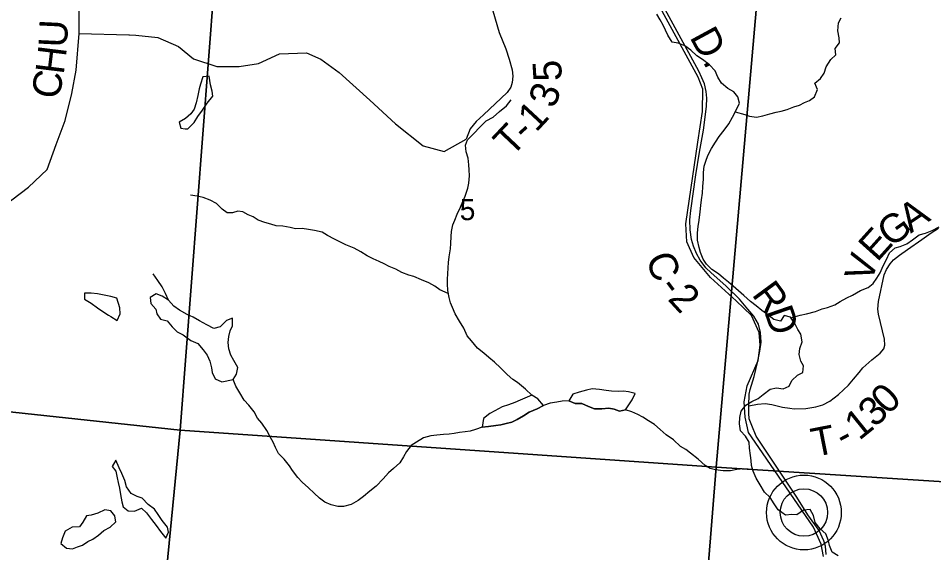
# Model space of a CAD drawing. Extents: x 0 to 42, y 0 to 22.
# Drawn here: x 5.439 to 6.349, y 16.58 to 17.112 of the extents above; entities that cross this region are included whole.
import ezdxf

# ---------------------------------------------------------------- set-up
doc = ezdxf.new("R2010")
doc.units = 0
for name, color, linetype in [('GM_X_County_Road', 7, 'Continuous'), ('GM_X_County_Road_Text', 7, 'Continuous'), ('GM_X_Minor_Lake', 7, 'Continuous'), ('GM_X_Minor_River', 7, 'Continuous'), ('GM_X_Rail_Line', 7, 'Continuous'), ('GM_X_Section', 7, 'Continuous'), ('GM_X_Section_Text', 7, 'Continuous'), ('GM_X_Township_Road', 7, 'Continuous'), ('GM_X_Township_Road_Text', 7, 'Continuous'), ('GM_X_Unincorporated', 7, 'Continuous'), ('GM_X_Unincorporated_Location', 7, 'Continuous')]:
    doc.layers.add(name, color=color, linetype=linetype)

msp = doc.modelspace()

# ---------------------------------------------------------------- linework, layer by layer
at = {"layer": 'GM_X_County_Road'}
msp.add_lwpolyline([(6.24237, 16.57834), (6.24164, 16.58663), (6.24003, 16.59225), (6.23522, 16.60227), (6.22412, 16.61791), (6.21303, 16.63543), (6.17849, 16.68713), (6.17274, 16.69623), (6.16813, 16.70676), (6.16578, 16.71352), (6.1653, 16.71899), (6.16523, 16.72628), (6.16569, 16.73809), (6.16677, 16.74257), (6.17067, 16.75545), (6.17416, 16.7707), (6.17625, 16.78068), (6.17756, 16.78978), (6.17679, 16.79943), (6.17482, 16.80754), (6.17043, 16.81566), (6.16429, 16.82268), (6.15586, 16.83252), (6.14247, 16.84582), (6.12767, 16.85854), (6.12268, 16.86354), (6.11692, 16.87115), (6.11341, 16.87795), (6.11034, 16.8853), (6.10836, 16.89177), (6.10683, 16.90153), (6.1065, 16.91151), (6.1076, 16.92072), (6.11264, 16.95603), (6.11615, 16.97884), (6.12034, 17.00047), (6.12328, 17.02413), (6.12361, 17.03225), (6.12284, 17.03915), (6.12109, 17.0465), (6.11856, 17.05275), (6.11549, 17.05922), (6.0725, 17.13851)], dxfattribs=at)
at = {"layer": 'GM_X_Minor_Lake'}
for points in [[(5.62834, 17.05424), (5.6221, 17.05367), (5.61984, 17.04628), (5.61852, 17.04155), (5.6172, 17.03491), (5.61569, 17.02771), (5.61343, 17.02146), (5.61022, 17.01672), (5.60494, 17.01217), (5.59871, 17.00857), (5.60041, 17.00251), (5.60459, 17.00205)], [(5.60459, 17.00205), (5.6074, 17.00175), (5.61363, 17.00819), (5.61721, 17.01407), (5.62174, 17.02051), (5.62665, 17.02753), (5.63212, 17.03435), (5.63155, 17.03928), (5.62985, 17.04572), (5.62834, 17.05424)], [(5.53666, 16.83348), (5.5308, 16.83499), (5.51758, 16.83764), (5.51116, 16.83839), (5.50455, 16.83858), (5.50456, 16.83252), (5.51117, 16.82835), (5.5174, 16.82399), (5.52382, 16.81964), (5.5284, 16.81666)], [(5.58799, 16.83157), (5.5816, 16.83539), (5.57575, 16.83766), (5.5697, 16.83424), (5.57046, 16.82818), (5.57556, 16.8225), (5.57632, 16.81776), (5.5801, 16.81246), (5.58671, 16.81094), (5.59162, 16.80507), (5.59653, 16.79996), (5.60258, 16.79693), (5.61032, 16.79144), (5.61712, 16.78841), (5.6226, 16.78197), (5.62638, 16.77685), (5.62903, 16.77079), (5.63092, 16.76416), (5.63149, 16.75943), (5.63432, 16.75317), (5.64093, 16.75033), (5.65228, 16.75246)], [(5.5284, 16.81666), (5.53081, 16.81509), (5.53705, 16.81131), (5.54006, 16.81775), (5.5395, 16.82381), (5.53666, 16.83348)], [(5.65228, 16.75246), (5.6557, 16.75794), (5.65686, 16.76456), (5.65311, 16.7714), (5.64992, 16.77672), (5.64806, 16.78317), (5.64733, 16.78943), (5.64812, 16.7953), (5.64946, 16.80098), (5.65175, 16.80608), (5.65159, 16.81347), (5.64573, 16.81141), (5.63946, 16.80481), (5.63322, 16.80313), (5.62625, 16.80695), (5.61889, 16.81078), (5.61248, 16.81441), (5.60664, 16.81727), (5.5991, 16.82148), (5.59326, 16.82567), (5.58799, 16.83157)], [(5.9, 16.70511), (5.90642, 16.70584), (5.91361, 16.70675), (5.91871, 16.70749), (5.92401, 16.70879), (5.9295, 16.71009), (5.93499, 16.71272), (5.94124, 16.71648), (5.94693, 16.72006), (5.95469, 16.72324), (5.96112, 16.72662), (5.9553, 16.73328), (5.94946, 16.73691)], [(5.94946, 16.73691), (5.93799, 16.73186), (5.93251, 16.72978), (5.92628, 16.7275), (5.91986, 16.72523), (5.91269, 16.72144), (5.90759, 16.71878), (5.90136, 16.71366), (5.9, 16.70511)], [(6.04256, 16.72228), (6.04922, 16.73228), (6.05224, 16.73853), (6.04544, 16.74042), (6.04053, 16.74099), (6.03562, 16.74061), (6.02882, 16.74098), (6.02353, 16.74174), (6.01673, 16.7425), (6.00956, 16.74325), (6.0037, 16.74211), (5.99653, 16.74003), (5.99011, 16.73813), (5.98609, 16.73125)], [(5.98609, 16.73125), (5.99269, 16.72857), (5.99931, 16.72854), (6.00572, 16.72567), (6.01195, 16.72336), (6.01913, 16.72352), (6.02593, 16.72406), (6.03122, 16.72309), (6.0365, 16.72098), (6.04256, 16.72228)], [(5.5356, 16.67243), (5.53201, 16.66618), (5.5356, 16.66144), (5.53711, 16.65481), (5.53806, 16.65007), (5.53938, 16.64458), (5.54014, 16.63814), (5.54147, 16.63075), (5.54298, 16.62601), (5.54808, 16.62204), (5.55412, 16.62166), (5.56111, 16.62469), (5.56621, 16.61996), (5.57103, 16.6134)], [(5.57103, 16.6134), (5.57566, 16.60746), (5.58, 16.60121), (5.58529, 16.59458), (5.58793, 16.60083), (5.58699, 16.60576), (5.58189, 16.61239), (5.57773, 16.61826), (5.57414, 16.62356), (5.56772, 16.6283), (5.56186, 16.63436), (5.55676, 16.63625), (5.55091, 16.63928), (5.54637, 16.64591), (5.54448, 16.65216), (5.54146, 16.65898), (5.539, 16.66485), (5.5356, 16.67243)], [(5.53503, 16.61478), (5.53468, 16.61711), (5.53071, 16.62184), (5.52466, 16.62298), (5.51768, 16.61975), (5.51126, 16.61767), (5.50635, 16.61691), (5.50276, 16.61065), (5.49937, 16.60592), (5.49238, 16.60553), (5.48539, 16.60155), (5.48257, 16.59511), (5.48106, 16.58943)], [(5.48106, 16.58943), (5.48653, 16.58469), (5.49258, 16.58412), (5.49749, 16.58621), (5.50259, 16.58792), (5.50787, 16.59133), (5.51278, 16.59361), (5.51825, 16.59778), (5.52373, 16.60232), (5.53015, 16.60555), (5.53562, 16.61085), (5.53503, 16.61478)]]:
    msp.add_lwpolyline(points, dxfattribs=at)
at = {"layer": 'GM_X_Minor_River'}
for points in [[(6.1203, 16.9584), (6.12071, 16.96484), (6.12243, 16.96976), (6.12453, 16.97524), (6.12815, 16.98224), (6.13215, 16.98866), (6.13577, 16.99414), (6.14071, 17.00056), (6.14546, 17.0068), (6.14889, 17.01341), (6.15289, 17.02098), (6.15613, 17.02759), (6.15446, 17.03385), (6.15051, 17.0388), (6.14448, 17.04205), (6.13807, 17.04719), (6.13432, 17.05327), (6.13189, 17.05954), (6.12606, 17.06544), (6.11909, 17.07097), (6.11344, 17.07459), (6.1076, 17.08012), (6.10157, 17.08431), (6.09516, 17.08718), (6.08893, 17.08797), (6.08461, 17.095), (6.08255, 17.09994), (6.08012, 17.10507), (6.07712, 17.1102), (6.07393, 17.1159)], [(6.15176, 17.01884), (6.16118, 17.01601), (6.16609, 17.01466), (6.17289, 17.01349), (6.17913, 17.01498), (6.18632, 17.01684), (6.19237, 17.01852), (6.19748, 17.01964), (6.20353, 17.02112), (6.21016, 17.02375), (6.21565, 17.02543), (6.22076, 17.02806), (6.22568, 17.03012), (6.23061, 17.03389), (6.23348, 17.04089), (6.23105, 17.04734), (6.23655, 17.05205), (6.24016, 17.05734), (6.24208, 17.06359), (6.24684, 17.07077), (6.25177, 17.07548), (6.25123, 17.08174), (6.2556, 17.0874), (6.25505, 17.09252), (6.25376, 17.09954), (6.25455, 17.10731), (6.25722, 17.11241)], [(5.96112, 16.72662), (5.9553, 16.73328), (5.94946, 16.73691), (5.94306, 16.74281), (5.93534, 16.74948), (5.93044, 16.75253), (5.92498, 16.75748), (5.91839, 16.76414), (5.91218, 16.76986), (5.90672, 16.77443), (5.90183, 16.77881), (5.89524, 16.78358), (5.88941, 16.79099), (5.88527, 16.79613), (5.88172, 16.80353), (5.87759, 16.81075), (5.87327, 16.81797), (5.87066, 16.82405), (5.8686, 16.82898), (5.86711, 16.83429), (5.86582, 16.84093), (5.86547, 16.84775), (5.86568, 16.85249), (5.86589, 16.8578), (5.86629, 16.86367), (5.86669, 16.86897), (5.86728, 16.87446), (5.86845, 16.88261), (5.86904, 16.88772), (5.86926, 16.89473), (5.86947, 16.89985), (5.87101, 16.90628), (5.87273, 16.9112), (5.87522, 16.91706), (5.87846, 16.92387), (5.88075, 16.92973), (5.88323, 16.93503), (5.88572, 16.94279), (5.88669, 16.9479), (5.88729, 16.9551), (5.88712, 16.96116), (5.88677, 16.96609), (5.88623, 16.97272), (5.88418, 16.97918), (5.88345, 16.98581), (5.88536, 16.99092), (5.89239, 16.9979), (5.89694, 17.00299), (5.90396, 17.00979), (5.91097, 17.01354), (5.91742, 17.01901), (5.92425, 17.02485), (5.929, 17.0309)], [(6.25414, 16.57714), (6.2483, 16.58096), (6.24549, 16.58741), (6.24457, 16.59215), (6.24176, 16.59898), (6.23612, 16.60413), (6.23142, 16.6104), (6.22975, 16.61742), (6.22637, 16.62331), (6.21976, 16.62258), (6.21293, 16.61806), (6.20802, 16.61827), (6.20178, 16.61754), (6.19462, 16.62288), (6.19049, 16.62877), (6.18636, 16.63504), (6.18072, 16.64056), (6.17659, 16.64778), (6.17265, 16.65443), (6.16947, 16.66127), (6.16798, 16.66696), (6.16762, 16.67207), (6.16689, 16.677), (6.16598, 16.68421), (6.16563, 16.69027), (6.16187, 16.69616), (6.15717, 16.70149), (6.15588, 16.70832), (6.15647, 16.71475), (6.15763, 16.721), (6.16219, 16.72704), (6.16845, 16.73062), (6.1747, 16.73362), (6.17963, 16.73758), (6.18645, 16.74304), (6.19288, 16.74434), (6.19949, 16.74317), (6.20536, 16.74599), (6.20803, 16.75166), (6.21373, 16.75675), (6.21903, 16.75938), (6.21962, 16.76619), (6.217, 16.77094), (6.21552, 16.77758), (6.21611, 16.78345), (6.21822, 16.78989), (6.21712, 16.79766), (6.21411, 16.80241), (6.21112, 16.8083), (6.20661, 16.81457), (6.20038, 16.81611), (6.19695, 16.81063), (6.19016, 16.81237), (6.18432, 16.81675), (6.1781, 16.82114), (6.17245, 16.8259), (6.1668, 16.8301), (6.16021, 16.83619), (6.15231, 16.84305), (6.14515, 16.84933), (6.14026, 16.85333), (6.13517, 16.85771), (6.12839, 16.8621), (6.12312, 16.86724), (6.11993, 16.87218), (6.11731, 16.87883), (6.11601, 16.88376), (6.11415, 16.89116), (6.11418, 16.89836), (6.11497, 16.9048), (6.11594, 16.91105), (6.11692, 16.91938), (6.11752, 16.92563), (6.11811, 16.93112), (6.11908, 16.93775), (6.11968, 16.94438), (6.12027, 16.95177), (6.1203, 16.9584)], [(5.86636, 16.83816), (5.85788, 16.84191), (5.85298, 16.84535), (5.84695, 16.84879), (5.83979, 16.85185), (5.83205, 16.85492), (5.82714, 16.85645), (5.82016, 16.85914), (5.81413, 16.86239), (5.80753, 16.86507), (5.80263, 16.86755), (5.79753, 16.87004), (5.7915, 16.87253), (5.78565, 16.87559), (5.77925, 16.87941), (5.77284, 16.88304), (5.76454, 16.88649), (5.75794, 16.88974), (5.75303, 16.89222), (5.74625, 16.89585), (5.74078, 16.8991), (5.73342, 16.90065), (5.72719, 16.90181), (5.72095, 16.9026), (5.71434, 16.90244), (5.70905, 16.9036), (5.70169, 16.90496), (5.69508, 16.90556), (5.68979, 16.90691), (5.68394, 16.90864), (5.67734, 16.91113), (5.67225, 16.91438), (5.66735, 16.91648), (5.66188, 16.91935), (5.65697, 16.91994), (5.65167, 16.91826), (5.64638, 16.91828), (5.6413, 16.9221), (5.63584, 16.92762), (5.62962, 16.93087), (5.62245, 16.93374), (5.61641, 16.93509), (5.6098, 16.93607)], [(6.20703, 16.81397), (6.21644, 16.81661), (6.22268, 16.81791), (6.23158, 16.82033), (6.2382, 16.82276), (6.2435, 16.82426), (6.25069, 16.82687), (6.25619, 16.83026), (6.26263, 16.83364), (6.26831, 16.83646), (6.27645, 16.84116), (6.28403, 16.84416), (6.28896, 16.84792), (6.29276, 16.85321), (6.2958, 16.8585), (6.29905, 16.8655), (6.3021, 16.87193), (6.30534, 16.87854), (6.31084, 16.88345), (6.31576, 16.88494), (6.32239, 16.88737), (6.32826, 16.89151), (6.33471, 16.8966), (6.34114, 16.89828), (6.34777, 16.90071), (6.35459, 16.90428)], [(5.65175, 16.80608), (5.65159, 16.81347), (5.64573, 16.81141), (5.63946, 16.80481), (5.63322, 16.80313), (5.62625, 16.80695), (5.61889, 16.81078), (5.61248, 16.81441), (5.60664, 16.81727), (5.5991, 16.82148), (5.59326, 16.82567), (5.58799, 16.83157), (5.58519, 16.83821), (5.58162, 16.84467), (5.57749, 16.85114), (5.5728, 16.85779)], [(6.16902, 16.66298), (6.16041, 16.66377), (6.15341, 16.66304), (6.14698, 16.66175), (6.13961, 16.66159), (6.13225, 16.66276), (6.12696, 16.66392), (6.12187, 16.66698), (6.11491, 16.67345), (6.10737, 16.67917), (6.10248, 16.68298), (6.0972, 16.68603), (6.09043, 16.69251), (6.08308, 16.69746), (6.07724, 16.7028), (6.07141, 16.70775), (6.06556, 16.71157), (6.05991, 16.715), (6.05501, 16.71768), (6.04878, 16.72055), (6.04256, 16.72228), (6.0365, 16.72098), (6.03122, 16.72309), (6.02593, 16.72406), (6.01913, 16.72352), (6.01195, 16.72336), (6.00572, 16.72567), (5.99931, 16.72854), (5.99269, 16.72857), (5.98609, 16.73125), (5.97967, 16.7309), (5.97437, 16.73016), (5.96756, 16.72887), (5.96113, 16.72662), (5.95469, 16.72324), (5.94693, 16.72006), (5.94124, 16.71648), (5.93499, 16.71272), (5.9295, 16.71009), (5.92401, 16.70879), (5.91871, 16.70749), (5.91361, 16.70675), (5.90642, 16.70584), (5.9, 16.70511), (5.89337, 16.70287), (5.88807, 16.70119), (5.88297, 16.70045), (5.87748, 16.69972), (5.87219, 16.69898), (5.86709, 16.69825), (5.8616, 16.6977), (5.85499, 16.69716), (5.84894, 16.69662), (5.84175, 16.69457), (5.83474, 16.69025), (5.82943, 16.68705), (5.82468, 16.68101), (5.82182, 16.67571), (5.81802, 16.66967), (5.81195, 16.66401), (5.80702, 16.65986), (5.8017, 16.65364), (5.79467, 16.64647), (5.78842, 16.64138), (5.78216, 16.6361), (5.77685, 16.63215), (5.76984, 16.62839), (5.76227, 16.62615), (5.7566, 16.62617), (5.75, 16.62791), (5.74358, 16.6304), (5.73812, 16.63459), (5.73304, 16.63935), (5.72721, 16.64487), (5.72099, 16.6504), (5.71667, 16.65515), (5.71141, 16.662), (5.7084, 16.66675), (5.70295, 16.6734), (5.6975, 16.67911), (5.69431, 16.685), (5.69207, 16.69013), (5.68963, 16.69488), (5.68569, 16.70171), (5.681, 16.70912), (5.67649, 16.71426), (5.67311, 16.72034), (5.66785, 16.72718), (5.66315, 16.73213), (5.65902, 16.73916), (5.65508, 16.74581), (5.65228, 16.75246), (5.6557, 16.75794), (5.65686, 16.76456), (5.65311, 16.7714), (5.64992, 16.77672), (5.64806, 16.78317), (5.64733, 16.78943), (5.64812, 16.7953), (5.64946, 16.80098), (5.65175, 16.80608)]]:
    msp.add_lwpolyline(points, dxfattribs=at)
at = {"layer": 'GM_X_Rail_Line'}
msp.add_lwpolyline([(6.2396, 16.57648), (6.23733, 16.58873), (6.22972, 16.60565), (6.17168, 16.69011), (6.16505, 16.69995), (6.16158, 16.71508), (6.16073, 16.73031), (6.16373, 16.74613), (6.17473, 16.77152), (6.17642, 16.78675), (6.17558, 16.79944), (6.16796, 16.81637), (6.15274, 16.83076), (6.12706, 16.85406), (6.11044, 16.87392), (6.10375, 16.88957), (6.10279, 16.90738), (6.11447, 16.98872), (6.11929, 17.01929), (6.11967, 17.04126), (6.11496, 17.0534), (6.06714, 17.14125)], dxfattribs=at)
at = {"layer": 'GM_X_Section'}
for points in [[(5.09837, 17.26445), (5.63895, 17.21787), (5.59959, 16.70229), (5.05068, 16.76119), (5.07281, 16.99321)], [(5.63895, 17.21787), (5.77059, 17.20699), (6.17708, 17.17339), (6.13279, 16.66538), (5.59959, 16.70229)], [(6.27444, 17.16575), (6.70346, 17.13156), (6.66411, 16.63113), (6.13279, 16.66538), (6.17708, 17.17339)], [(5.59959, 16.70229), (5.55229, 16.21494), (5.00319, 16.26475), (5.02417, 16.48692), (5.05068, 16.76119)], [(6.13279, 16.66538), (6.09307, 16.16969), (5.55229, 16.21494), (5.59959, 16.70229)], [(6.13279, 16.66538), (6.66411, 16.63113), (6.61604, 16.129), (6.09307, 16.16969)]]:
    msp.add_lwpolyline(points, close=True, dxfattribs=at)
at = {"layer": 'GM_X_Township_Road'}
msp.add_line((5.49927, 17.09684), (5.54871, 17.0954), dxfattribs=at)
for points in [[(5.92385, 17.19002), (5.9209, 17.18019), (5.9182, 17.17558), (5.91413, 17.14203), (5.91192, 17.12705), (5.91063, 17.11927), (5.91697, 17.09769), (5.92362, 17.08143), (5.92698, 17.07117), (5.92978, 17.06071), (5.93071, 17.05436), (5.92997, 17.04802), (5.92866, 17.04335), (5.92493, 17.03813), (5.90122, 17.01591), (5.89412, 17.00919), (5.88796, 17.00191), (5.88404, 16.99164)], [(5.42382, 16.92491), (5.4489, 16.94379), (5.46736, 16.96151), (5.47634, 16.98619), (5.48513, 17.01012), (5.49182, 17.03707), (5.49626, 17.06041), (5.49927, 17.09684), (5.49932, 17.09739), (5.49939, 17.14261)], [(5.54871, 17.0954), (5.5492, 17.09538), (5.55569, 17.0952), (5.57746, 17.09284), (5.59811, 17.08365), (5.61292, 17.07159), (5.63603, 17.06392), (5.65835, 17.06403), (5.67744, 17.06678), (5.69839, 17.07655), (5.72525, 17.07743), (5.73965, 17.07125), (5.75787, 17.05788), (5.78844, 17.03035), (5.81388, 17.00697), (5.8414, 16.98511), (5.86224, 16.97933), (5.88404, 16.99164)], [(6.16523, 16.72628), (6.17383, 16.72815), (6.18151, 16.7288), (6.18831, 16.7276), (6.19335, 16.7265), (6.19875, 16.72502), (6.20597, 16.72395), (6.21026, 16.72346), (6.22186, 16.72385), (6.23181, 16.72522), (6.23893, 16.72726), (6.24595, 16.73097), (6.25443, 16.7377), (6.26438, 16.74696), (6.26945, 16.75281), (6.27491, 16.75964), (6.27862, 16.76422), (6.28778, 16.77222), (6.29598, 16.77868), (6.29947, 16.78292), (6.30059, 16.78679), (6.30009, 16.79252), (6.29423, 16.81769), (6.29373, 16.82268), (6.29423, 16.83016), (6.29996, 16.85683), (6.30221, 16.86206), (6.30582, 16.86767), (6.30931, 16.87165), (6.31504, 16.87627), (6.32314, 16.88188), (6.33747, 16.89172), (6.3467, 16.89845), (6.35393, 16.90294)]]:
    msp.add_lwpolyline(points, dxfattribs=at)
at = {"layer": 'GM_X_Unincorporated'}
for radius in [0.0372, 0.02358]:
    msp.add_circle((6.2201, 16.62023), radius, dxfattribs=at)
at = {"layer": 'GM_X_Unincorporated_Location'}
msp.add_line((6.2201, 16.62023), (6.2201, 16.62023), dxfattribs=at)

# ---------------------------------------------------------------- texts
at = {"layer": 'GM_X_County_Road_Text'}
for s, height, rotation, p in [('D.', 0.028409, 298.43547, (6.10596, 17.09323)), ('C', 0.02841, 291.34772, (6.06219, 16.87296)), ('-', 0.02841, 307.12829, (6.07484, 16.8438)), ('2', 0.02841, 312.62473, (6.08379, 16.83221)), ('R', 0.02841, 306.36484, (6.16758, 16.83701)), ('D', 0.02841, 289.06622, (6.18036, 16.82022))]:
    msp.add_text(s, height=height, rotation=rotation, dxfattribs=at).set_placement(p)
at = {"layer": 'GM_X_Section_Text'}
msp.add_text('5', height=0.02093, rotation=0.00001, dxfattribs=at).set_placement((5.87772, 16.91106))
at = {"layer": 'GM_X_Township_Road_Text'}
for s, rotation, p in [('U', 87.34287, (5.48701, 17.08244)), ('H', 83.0202, (5.48377, 17.0553)), ('5', 93.50922, (5.97957, 17.04999)), ('C', 78.83703, (5.4789, 17.03017)), ('3', 70.7362, (5.97212, 17.02136)), ('1', 47.09963, (5.95366, 16.99767)), ('T', 46.66998, (5.92933, 16.97303)), ('-', 43.01251, (5.94357, 16.98815)), ('A', 33.58297, (6.32628, 16.89751)), ('G', 34.91264, (6.30593, 16.8833)), ('E', 47.99239, (6.29299, 16.86864)), ('V', 72.05118, (6.28685, 16.84757)), ('0', 44.87249, (6.30375, 16.71651)), ('3', 43.73235, (6.29066, 16.70398)), ('1', 38.84499, (6.27505, 16.69126)), ('T', 11.11327, (6.23045, 16.6754)), ('-', 28.07242, (6.2599, 16.68256))]:
    msp.add_text(s, height=0.02841, rotation=rotation, dxfattribs=at).set_placement(p)

doc.saveas('drawing.dxf')
